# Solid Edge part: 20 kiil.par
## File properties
Author: Henri
Template: Normal.par
Last saved by: Henri
Revision: 4
Application: Solid Edge
Accuracy: 0,990
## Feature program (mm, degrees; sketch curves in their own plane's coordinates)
make body feature "unnamed MakeBodyFeature 1"
sketch for "ExtrudedProtrusion_5" plane through (-12.5, 2.7237, 0) normal (0, 0, 1) x-axis (1, 0, 0)
extrude "ExtrudedProtrusion_5" add finite 7.5 along +normal
fillet "Round_7" radius 2
fillet "Round_9" radius 1
body pattern "unnamed BodyPattern 1"
pattern "unnamed Pattern 1"
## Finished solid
Body 1: solid body, 28 faces, 97 edges, 71 vertices.
  Faces by surface: spline 12, blend 10, plane 3, torus 2, cylinder 1
  Edges by curve: intersection 56, curve on surface 32, circle 9
Body 2: solid body, 8 faces, 20 edges, 14 vertices.
  Faces by surface: spline 6, plane 2
  Edges by curve: curve on surface 19, line 1
Bounding box of the edges (mm; curved faces can reach further): 75.000 x 10.661 x 67.838, from (-50, -5.2375, -60.3382) to (25, 5.4234, 7.5).
Cylindrical faces by radius (mm): R2.5 x1
Toroidal faces (ring radius, tube radius in mm): R3.5 r1 x2
Planar faces by outward normal: +z 4, -y 1
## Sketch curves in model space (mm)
arc centre (0, 0, 0) radius 2.5 from (-2.5, 0, 0) through (0.0741, 2.4989, 0) to (2.5, 0, 0)
line (-2.5, 0, 0) -> (2.5, 0, 0)
line (0, 5, 0) -> (0, 0, -60)
line (0, -8.2596, -50) -> (0, -19.8229, -50)
line (-50, 0, 0) -> (25, 0, 0)
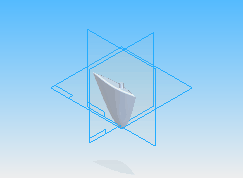
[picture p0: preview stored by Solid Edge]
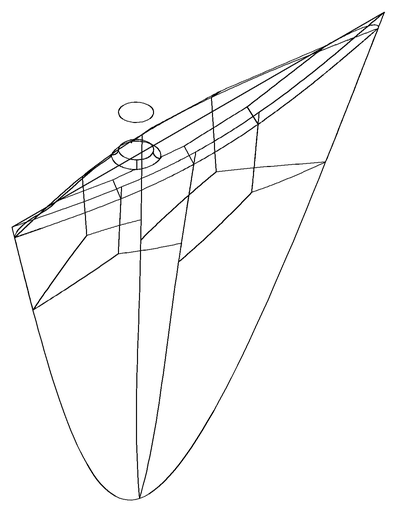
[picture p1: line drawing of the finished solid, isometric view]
